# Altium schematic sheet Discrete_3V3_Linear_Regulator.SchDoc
size A; SheetNumber: 1; SheetTotal: 1
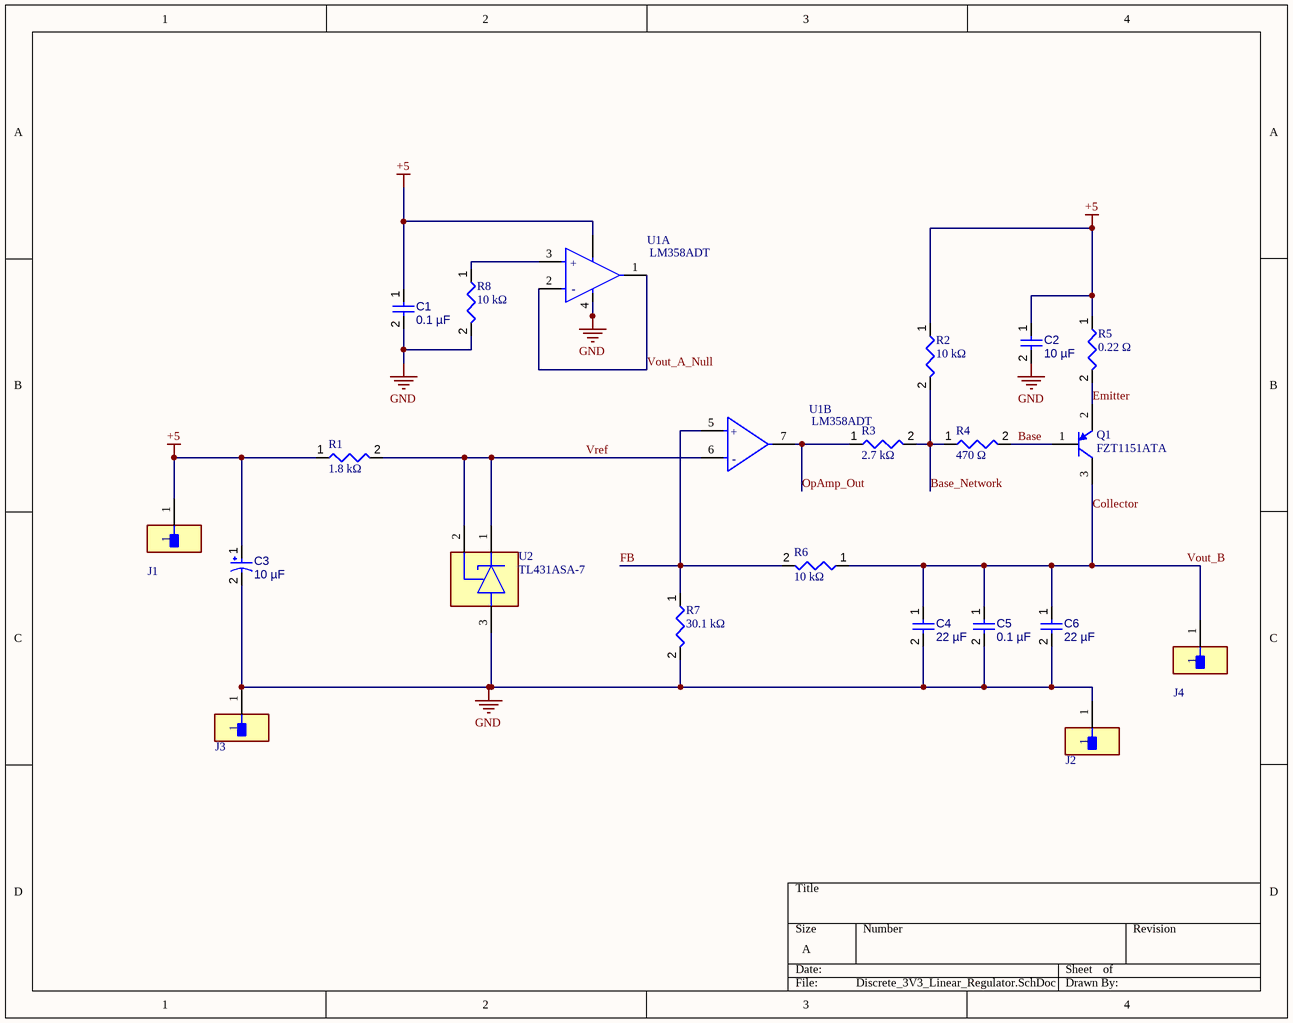
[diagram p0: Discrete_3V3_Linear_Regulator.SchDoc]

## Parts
C1  0.1 µF  [CAP_0805_IPC_M]
C2  10 µF  [CAP_0805_IPC_M]
C3  10 µF  [WCAP-PSLP_D5H5.5]
C4  22 µF  [CAP_0805_IPC_M]
C5  0.1 µF  [CAP_0805_IPC_M]
C6  22 µF  [CAP_0805_IPC_M]
J1  HTSW-101-07-L-S  [FP-HTSW-101-07-L-S-MFG]  (value not drawn)
J2  HTSW-101-07-L-S  [FP-HTSW-101-07-L-S-MFG]  (value not drawn)
J3  HTSW-101-07-L-S  [FP-HTSW-101-07-L-S-MFG]  (value not drawn)
J4  HTSW-101-07-L-S  [FP-HTSW-101-07-L-S-MFG]  (value not drawn)
Q1  FZT1151ATA  [SOT223_4P_TAB_IPC_L]
R1  1.8 kΩ  [RES_0805_IPC_M]
R2  10 kΩ  [RES_0805_IPC_M]
R3  2.7 kΩ  [RES_0805_IPC_M]
R4  470 Ω  [RES_0805_IPC_M]
R5  0.22 Ω  [RES_1206_IPC_M]
R6  10 kΩ  [RES_0805_IPC_M]
R7  30.1 kΩ  [RES_0805_IPC_M]
R8  10 kΩ  [RES_0805_IPC_M]
U1  LM358ADT  [FP-SO8-IPC_A]  (parts A,B of 2)
U2  TL431ASA-7  [FP-SOT23-MFG]

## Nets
+5: C1.1 C2.1 C3.1 J1.1 R1.1 R2.1 R5.1 U1.8(VCC+)
GND: C1.2 C2.2 C3.2 C4.2 C5.2 C6.2 J2.1 J3.1 R7.2 R8.2 U1.4(VCC-) U2.3(A)
Base: Q1.1(B) R4.2
Base_Network: R2.2 R3.2 R4.1
Collector: C4.1 C5.1 C6.1 J4.1 Q1.3(C) R6.1  [also labelled Vout_B]
Emitter: Q1.2(E) R5.2
FB: R6.2 R7.1 U1.5(In2+)
OpAmp_Out: R3.1 U1.7(Out2)
Vout_A_Null: U1.1(Out1) U1.2(In1-)
Vref: R1.2 U1.6(In2-) U2.1(C) U2.2(REF)
NetR8_1: R8.1 U1.3(In1+)

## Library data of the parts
C1 C2 C4 C5 = C: Generic non-polarized capacitor (ceramic/film), value defined per instance
C3 = C_POL: WCAP-PSLP Radial Can - SMD Aluminum Polymer Capacitor 0.197Dia 5.00mm ±20% 100muF 10V; Manufacturer: Wurth Elektronik; Manufacturer Part Number: 875105242010; Value: 100µF; Dissipation Factor: 8%; ESR (Equivalent Series Resistance): 30mΩ; Leakage Current: 300µA; Life (Hours): 2000hours; Pitch: 5.3mm; Polarity: Polar; Ripple Current: 1.97A
C6 = C: Adjustable based on output requirements
J1-J4 = CMP-02766-001464-1: CONN HEADER VERT 1POS; Number of Contacts: 1; Max Voltage Rating (AC): 550V; Gender: Male; Max Current Rating: 7.6A
Q1 = BJT_PNP: Generic PNP BJT transistor symbol (discrete)
R1-R8 = R: Generic resistor, value defined per instance
U1 = CMP-12131-000002-1: IC OPAMP GP 2 CIRCUIT 8SO; Manufacturer: STMicroelectronics; Min Dual Supply Voltage: 1.5V; Standoff Height: 0.1mm; Number Of Channels: 2; Max Supply Voltage: 30V; Nominal Supply Current: 0.7mA; Max Dual Supply Voltage: 15V; Voltage Gain: 100V/mV; Gain Bandwidth: 1.1MHz; Output Current Per Channel: 50-20000uA; Input Offset Voltage: 1mV; Input Bias Current: 0.02uA; Max Junction Temp: +150°C; Min Supply Voltage: 3V
U2 = CMP-12755-000001-1: IC VREF SHUNT ADJ SOT23-3; Manufacturer: DIODES INC.; Standoff Height: 0.013mm; Max Power Dissipation: 330mW; Max Junction Temp: +150°C; Output Type: AdjustableProgrammable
